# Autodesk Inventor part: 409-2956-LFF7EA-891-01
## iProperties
Created: 2011-01
Part Number: 409-2956-LFF7EA-891-01
Material: 1" LIQUID TIGHT
Document SubType Name: Modeling
Designer: S. Boerckel
Engineer: Steve Boerckel
Mass: 358.747 g
Surface Area: 1136.16 cm^2
Volume: 256.248 cm^3
Density: 1.4 g/cm^3
Description: MOTOR LIQUID TIGHT
LGTH: 22.534 in
SMR: =<MATERIAL>
Author: S. Boerckel
Revision Number: 0
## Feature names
1. Sweep1
